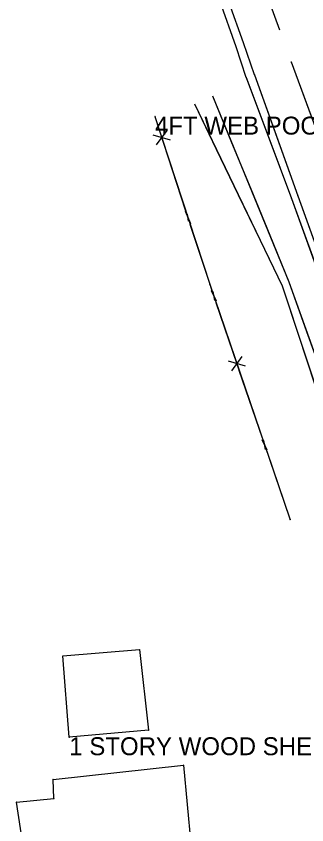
# Model space of a CAD drawing. Extents: x 1050807 to 1053552, y 395828 to 398415.
# Drawn here: x 1052487.3 to 1052568.2, y 396242.6 to 396468 of the extents above; entities that cross this region are included whole.
import ezdxf

# ---------------------------------------------------------------- set-up
doc = ezdxf.new("R2010")
doc.units = 0
for name, color, linetype in [('S_BUILDING', 7, 'Continuous'), ('S_BUILDING_ANNOT', 7, 'Continuous'), ('S_DITCHLINE', 7, 'Continuous'), ('S_EDGE_PAVEMENT', 7, 'Continuous'), ('S_FENCE', 7, 'Continuous'), ('S_FENCE_ANNOT', 7, 'Continuous'), ('S_MSC_PT_SYM', 7, 'Continuous'), ('S_PAVEMENT_CROWN', 7, 'Continuous'), ('S_RDW_PT_SYM', 7, 'Continuous'), ('S_SHOULDER', 7, 'Continuous'), ('S_STR_PT_SYM', 7, 'Continuous')]:
    doc.layers.add(name, color=color, linetype=linetype)

msp = doc.modelspace()

# ---------------------------------------------------------------- linework, layer by layer
at = {"layer": 'S_BUILDING'}
for p, q in [((1052500.3, 396289.7), (1052521.62, 396291.48)), ((1052502.05, 396267.03), (1052500.3, 396289.7)), ((1052521.62, 396291.48), (1052524.08, 396268.98)), ((1052524.08, 396268.98), (1052502.05, 396267.03)), ((1052497.56, 396255.26), (1052533.83, 396259.23)), ((1052533.83, 396259.23), (1052536.9, 396226.54)), ((1052497.78, 396250), (1052497.56, 396255.26)), ((1052487.31, 396248.91), (1052497.78, 396250)), ((1052491.51, 396221.91), (1052487.31, 396248.91))]:
    msp.add_line(p, q, dxfattribs=at)
at = {"layer": 'S_DITCHLINE'}
for p, q in [((1052541.96, 396445.77), (1052563.19, 396393.98)), ((1052536.89, 396443.57), (1052561.35, 396392.88)), ((1052563.19, 396393.98), (1052583.04, 396338.48)), ((1052561.35, 396392.88), (1052579.55, 396337.67))]:
    msp.add_line(p, q, dxfattribs=at)
for points in [[(1052541.96, 396445.77), (1052547.27, 396432.82), (1052552.57, 396419.87), (1052557.88, 396406.93), (1052563.19, 396393.98), (1052568.15, 396380.1), (1052573.12, 396366.23), (1052578.08, 396352.35), (1052583.04, 396338.48), (1052589.28, 396319.07), (1052595.52, 396299.66)], [(1052536.89, 396443.57), (1052543, 396430.89), (1052549.12, 396418.22), (1052555.23, 396405.55), (1052561.35, 396392.88), (1052565.9, 396379.08), (1052570.45, 396365.27), (1052575, 396351.47), (1052579.55, 396337.67), (1052586.53, 396318.21), (1052593.51, 396298.76)]]:
    msp.add_lwpolyline(points, dxfattribs=at)
at = {"layer": 'S_EDGE_PAVEMENT'}
for p, q in [((1052553.66, 396451.67), (1052565.68, 396417.96)), ((1052565.68, 396417.96), (1052579.04, 396380.75))]:
    msp.add_line(p, q, dxfattribs=at)
for points in [[(1052550.61, 396460.54), (1052542.56, 396482.95), (1052534.52, 396505.36), (1052527.08, 396526.36), (1052519.65, 396547.35), (1052514.14, 396562.84), (1052508.64, 396578.34), (1052503.13, 396593.83), (1052497.63, 396609.32)], [(1052553.66, 396451.67), (1052550.61, 396460.54)], [(1052553.66, 396451.67), (1052559.67, 396434.81), (1052565.68, 396417.96), (1052572.36, 396399.35), (1052579.04, 396380.75), (1052585.22, 396363.09), (1052591.4, 396345.43), (1052599.7, 396322.98), (1052607.79, 396300.33), (1052615.89, 396277.68), (1052623.98, 396255.21), (1052629.2, 396240.35)]]:
    msp.add_lwpolyline(points, dxfattribs=at)
at = {"layer": 'S_FENCE'}
for p, q in [((1052526.32, 396432.16), (1052529.34, 396436.1)), ((1052530.22, 396433.43), (1052525.45, 396434.82)), ((1052535.88, 396410.15), (1052534.38, 396413.52)), ((1052535.25, 396410.86), (1052535.01, 396412.82)), ((1052543.01, 396388.58), (1052541.63, 396391.47)), ((1052542.55, 396388.77), (1052542.09, 396391.28)), ((1052547.28, 396369.15), (1052550.23, 396373.17)), ((1052551.16, 396370.47), (1052546.36, 396371.85)), ((1052557.17, 396347.07), (1052555.79, 396349.97)), ((1052556.72, 396347.26), (1052556.25, 396349.78))]:
    msp.add_line(p, q, dxfattribs=at)
for points in [[(1052563.56, 396327.77), (1052541.24, 396393.19), (1052525.93, 396439.95)], [(1052534.53, 396413.7), (1052525.93, 396439.95)], [(1052527.23, 396435.98), (1052525.93, 396439.95)], [(1052534.53, 396413.7), (1052528.44, 396432.27)], [(1052541.86, 396391.38), (1052541.24, 396393.19), (1052535.74, 396409.98)], [(1052541.86, 396391.38), (1052541.24, 396393.19), (1052535.74, 396409.98)], [(1052555.84, 396350.41), (1052542.96, 396388.14)], [(1052548.11, 396373.05), (1052542.96, 396388.14)], [(1052555.84, 396350.41), (1052549.4, 396369.27)], [(1052563.56, 396327.77), (1052557.13, 396346.63)], [(1052563.56, 396327.77), (1052557.13, 396346.63)]]:
    msp.add_lwpolyline(points, dxfattribs=at)
at = {"layer": 'S_MSC_PT_SYM'}
for points in [[(1052525.93, 396440), (1052525.93, 396440.05), (1052525.93, 396440), (1052525.88, 396440), (1052525.93, 396440), (1052525.93, 396439.95), (1052525.93, 396440), (1052525.98, 396440)], [(1052541.19, 396393.19), (1052541.19, 396393.24), (1052541.19, 396393.19), (1052541.14, 396393.19), (1052541.19, 396393.19), (1052541.19, 396393.14), (1052541.19, 396393.19), (1052541.24, 396393.19)], [(1052563.56, 396327.72), (1052563.56, 396327.77), (1052563.56, 396327.72), (1052563.51, 396327.72), (1052563.56, 396327.72), (1052563.56, 396327.67), (1052563.56, 396327.72), (1052563.61, 396327.72)]]:
    msp.add_lwpolyline(points, dxfattribs=at)
at = {"layer": 'S_PAVEMENT_CROWN'}
msp.add_line((1052563.85, 396455.27), (1052576.21, 396421.5), dxfattribs=at)
for points in [[(1052560.66, 396464.06), (1052552.31, 396487.03), (1052543.96, 396509.99), (1052539.88, 396521.85), (1052535.8, 396533.71), (1052531.72, 396545.57), (1052527.64, 396557.43), (1052522.8, 396570.88), (1052517.97, 396584.32), (1052513.13, 396597.77), (1052508.29, 396611.21)], [(1052563.85, 396455.27), (1052570.03, 396438.38), (1052576.21, 396421.5), (1052582.81, 396403.17), (1052589.41, 396384.85), (1052595.83, 396366.9), (1052602.25, 396348.96), (1052609.91, 396326.87), (1052617.92, 396304.16), (1052625.94, 396281.45), (1052634.39, 396259.26), (1052639.65, 396244.64), (1052644.91, 396230.01)]]:
    msp.add_lwpolyline(points, dxfattribs=at)
at = {"layer": 'S_RDW_PT_SYM'}
for points in [[(1052563.85, 396455.27), (1052563.85, 396455.32), (1052563.85, 396455.27), (1052563.8, 396455.27), (1052563.85, 396455.27), (1052563.85, 396455.22), (1052563.85, 396455.27), (1052563.9, 396455.27)], [(1052551.32, 396450.93), (1052551.32, 396450.98), (1052551.32, 396450.93), (1052551.27, 396450.93), (1052551.32, 396450.93), (1052551.32, 396450.88), (1052551.32, 396450.93), (1052551.37, 396450.93)], [(1052553.66, 396451.67), (1052553.66, 396451.72), (1052553.66, 396451.67), (1052553.61, 396451.67), (1052553.66, 396451.67), (1052553.66, 396451.62), (1052553.66, 396451.67), (1052553.71, 396451.67)], [(1052563.9, 396417.22), (1052563.9, 396417.27), (1052563.9, 396417.22), (1052563.85, 396417.22), (1052563.9, 396417.22), (1052563.9, 396417.17), (1052563.9, 396417.22), (1052563.95, 396417.22)], [(1052565.68, 396417.96), (1052565.68, 396418.01), (1052565.68, 396417.96), (1052565.63, 396417.96), (1052565.68, 396417.96), (1052565.68, 396417.91), (1052565.68, 396417.96), (1052565.73, 396417.96)]]:
    msp.add_lwpolyline(points, dxfattribs=at)
at = {"layer": 'S_SHOULDER'}
for p, q in [((1052551.32, 396450.93), (1052563.9, 396417.22)), ((1052563.9, 396417.22), (1052577.38, 396380.03))]:
    msp.add_line(p, q, dxfattribs=at)
for points in [[(1052548.56, 396459.48), (1052543.95, 396472.24), (1052539.35, 396484.99), (1052534.75, 396497.74), (1052530.14, 396510.49), (1052525.9, 396522.82), (1052521.65, 396535.15), (1052517.4, 396547.48), (1052513.15, 396559.81), (1052505.87, 396579), (1052501.53, 396593.37), (1052497.18, 396607.74)], [(1052551.32, 396450.93), (1052548.56, 396459.48)], [(1052551.32, 396450.93), (1052557.61, 396434.07), (1052563.9, 396417.22), (1052570.64, 396398.62), (1052577.38, 396380.03), (1052583.62, 396362.39), (1052589.85, 396344.75), (1052597.76, 396322.39), (1052604.43, 396302.31)]]:
    msp.add_lwpolyline(points, dxfattribs=at)
at = {"layer": 'S_STR_PT_SYM'}
for points in [[(1052500.3, 396289.7), (1052500.3, 396289.75), (1052500.3, 396289.7), (1052500.25, 396289.7), (1052500.3, 396289.7), (1052500.3, 396289.65), (1052500.3, 396289.7), (1052500.35, 396289.7)], [(1052521.62, 396291.48), (1052521.62, 396291.53), (1052521.62, 396291.48), (1052521.57, 396291.48), (1052521.62, 396291.48), (1052521.62, 396291.43), (1052521.62, 396291.48), (1052521.67, 396291.48)], [(1052502.05, 396267.03), (1052502.05, 396267.08), (1052502.05, 396267.03), (1052502, 396267.03), (1052502.05, 396267.03), (1052502.05, 396266.98), (1052502.05, 396267.03), (1052502.1, 396267.03)], [(1052524.08, 396268.98), (1052524.08, 396269.03), (1052524.08, 396268.98), (1052524.03, 396268.98), (1052524.08, 396268.98), (1052524.08, 396268.93), (1052524.08, 396268.98), (1052524.13, 396268.98)], [(1052533.83, 396259.23), (1052533.83, 396259.28), (1052533.83, 396259.23), (1052533.78, 396259.23), (1052533.83, 396259.23), (1052533.83, 396259.18), (1052533.83, 396259.23), (1052533.88, 396259.23)], [(1052497.56, 396255.26), (1052497.56, 396255.31), (1052497.56, 396255.26), (1052497.51, 396255.26), (1052497.56, 396255.26), (1052497.56, 396255.21), (1052497.56, 396255.26), (1052497.61, 396255.26)], [(1052497.78, 396250), (1052497.78, 396250.05), (1052497.78, 396250), (1052497.73, 396250), (1052497.78, 396250), (1052497.78, 396249.95), (1052497.78, 396250), (1052497.83, 396250)], [(1052487.31, 396248.91), (1052487.31, 396248.96), (1052487.31, 396248.91), (1052487.26, 396248.91), (1052487.31, 396248.91), (1052487.31, 396248.86), (1052487.31, 396248.91), (1052487.36, 396248.91)]]:
    msp.add_lwpolyline(points, dxfattribs=at)

# ---------------------------------------------------------------- texts
at = {"layer": 'S_BUILDING_ANNOT'}
msp.add_text('1 STORY WOOD SHED', height=5, dxfattribs=at).set_placement((1052502.05, 396262.03))
at = {"layer": 'S_FENCE_ANNOT'}
msp.add_text('4FT WEB POOR', height=5, dxfattribs=at).set_placement((1052525.93, 396435))
msp.add_text('4FT WEB POOR', height=5, dxfattribs=at).set_placement((1052525.93, 396435))

doc.saveas('drawing.dxf')
